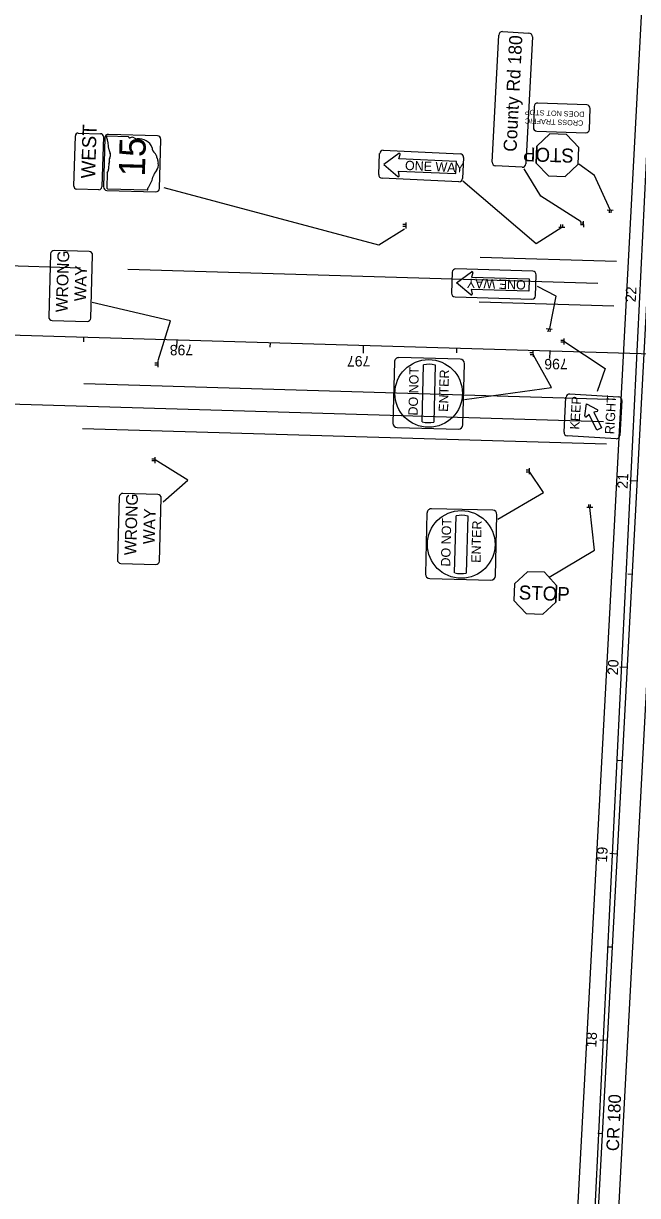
# Model space of a CAD drawing. Extents: x 1658454 to 1663955, y 480219 to 484109.
# Drawn here: x 1661070 to 1661399, y 482260 to 482888 of the extents above; entities that cross this region are included whole.
import ezdxf

# ---------------------------------------------------------------- set-up
doc = ezdxf.new("R2010")
doc.units = 0
for name, color, linetype in [('Default', 7, 'Continuous'), ('PM_P_CL_Double_Solid', 7, 'Continuous'), ('PM_P_Edge_Line', 7, 'Continuous'), ('PM_P_Lane_Line', 7, 'Continuous'), ('PM_X_Lane_Line', 7, 'Continuous'), ('PV_P_EOP', 7, 'Continuous'), ('RW_X_CL_50', 7, 'Continuous'), ('SC_Scratch1', 7, 'Continuous'), ('SN_X_Public', 7, 'Continuous'), ('SN_X_Text', 7, 'Continuous'), ('SV_X_CL_Survey_50', 7, 'Continuous'), ('SV_X_Text', 7, 'Continuous')]:
    doc.layers.add(name, color=color, linetype=linetype)

msp = doc.modelspace()

# ---------------------------------------------------------------- linework, layer by layer
at = {"layer": 'Default'}
for p, q in [((1661102.5, 482720.22), (1661102.43, 482717.83)), ((1661152.48, 482718.74), (1661152.36, 482714.74)), ((1661202.45, 482717.26), (1661202.38, 482714.86)), ((1661252.43, 482715.77), (1661252.31, 482711.77)), ((1661302.41, 482714.29), (1661302.34, 482711.89)), ((1661352.39, 482712.81), (1661352.27, 482708.81)), ((1661399.23, 482643.08), (1661395.24, 482643.3)), ((1661396.56, 482593.15), (1661394.17, 482593.28)), ((1661393.89, 482543.22), (1661389.9, 482543.44)), ((1661391.22, 482493.3), (1661388.82, 482493.42)), ((1661388.55, 482443.37), (1661384.55, 482443.58)), ((1661385.88, 482393.44), (1661383.48, 482393.57)), ((1661383.2, 482343.51), (1661379.21, 482343.72)), ((1661380.53, 482293.58), (1661378.13, 482293.71))]:
    msp.add_line(p, q, dxfattribs=at)
at = {"layer": 'PM_P_CL_Double_Solid'}
msp.add_line((1661344.46, 481619.54), (1661462.56, 483826.39), dxfattribs=at)
at = {"layer": 'PM_P_Edge_Line'}
for p, q in [((1661385.68, 482595.56), (1661398.13, 482828.23)), ((1661388.01, 482760.77), (1661315.12, 482762.93)), ((1661386.72, 482736.8), (1661314.41, 482738.94)), ((1661384.05, 482686.85), (1661102.66, 482695.21)), ((1661382.77, 482662.88), (1661101.95, 482671.22))]:
    msp.add_line(p, q, dxfattribs=at)
at = {"layer": 'PM_P_Lane_Line'}
msp.add_line((1661381.08, 482674.94), (1660395.32, 482704.21), dxfattribs=at)
at = {"layer": 'PM_X_Lane_Line'}
for p, q in [((1661100.95, 482757.29), (1660398.07, 482778.16)), ((1661378.1, 482749.06), (1661126.19, 482756.54))]:
    msp.add_line(p, q, dxfattribs=at)
at = {"layer": 'PV_P_EOP'}
for p, q in [((1661398.13, 482828.23), (1661448.64, 483772.06)), ((1661333.48, 481620.13), (1661385.68, 482595.56)), ((1661355.44, 481618.95), (1661407.64, 482594.38))]:
    msp.add_line(p, q, dxfattribs=at)
at = {"layer": 'RW_X_CL_50'}
msp.add_line((1661341.73, 481544.59), (1661467.43, 484100.93), dxfattribs=at)
at = {"layer": 'SC_Scratch1'}
for p, q in [((1661321.52, 482814.03), (1661325.01, 482882.1)), ((1661327.03, 482883.92), (1661341.17, 482883.2)), ((1661342.99, 482881.18), (1661339.5, 482813.1)), ((1661097.33, 482801.17), (1661098.14, 482828.16)), ((1661099.68, 482829.61), (1661111.67, 482829.26)), ((1661113.13, 482827.71), (1661112.33, 482800.72)), ((1661126.38, 482827.63), (1661115.22, 482827.95)), ((1661126.38, 482827.63), (1661126.38, 482827.63)), ((1661352.33, 482829.1), (1661345.38, 482822.55)), ((1661361.33, 482828.83), (1661352.33, 482829.1)), ((1661367.87, 482821.89), (1661361.33, 482828.83)), ((1661271.48, 482818.65), (1661263.42, 482812.83)), ((1661271.48, 482815.77), (1661272.21, 482818.14)), ((1661345.12, 482813.56), (1661345.38, 482822.55)), ((1661345.38, 482822.55), (1661345.12, 482813.56)), ((1661345.38, 482822.55), (1661345.12, 482813.56)), ((1661367.61, 482812.89), (1661367.87, 482821.89)), ((1661263.42, 482812.83), (1661270.94, 482806.35)), ((1661302.29, 482814.4), (1661271.48, 482815.77)), ((1661302, 482807.85), (1661302.29, 482814.4)), ((1661337.48, 482811.29), (1661323.34, 482812.01)), ((1661345.12, 482813.56), (1661351.66, 482806.61)), ((1661360.66, 482806.34), (1661367.61, 482812.89)), ((1661115.2, 482808.33), (1661114.97, 482800.1)), ((1661271.7, 482806.8), (1661271.19, 482809.21)), ((1661271.19, 482809.21), (1661302, 482807.85)), ((1661351.66, 482806.61), (1661360.66, 482806.34)), ((1661110.78, 482799.27), (1661098.79, 482799.63)), ((1661115.33, 482799.81), (1661136.66, 482799.21)), ((1661302.4, 482749.37), (1661310.37, 482755.29)), ((1661310, 482742.97), (1661302.4, 482749.37)), ((1661311.1, 482754.78), (1661310.42, 482752.41)), ((1661310.42, 482752.41), (1661341.24, 482751.49)), ((1661341.24, 482751.49), (1661341.04, 482744.93)), ((1661341.04, 482744.93), (1661310.22, 482745.85)), ((1661310.22, 482745.85), (1661310.77, 482743.43)), ((1661283.94, 482674.91), (1661284.7, 482705.52)), ((1661290.95, 482705.36), (1661290.19, 482674.75)), ((1661371.15, 482678.12), (1661372.09, 482684.54)), ((1661372.09, 482684.54), (1661377.81, 482681.48)), ((1661377.64, 482680.46), (1661375.87, 482680.17)), ((1661375.87, 482680.17), (1661380.1, 482671.78)), ((1661373.36, 482678.91), (1661372.08, 482677.65)), ((1661377.59, 482670.52), (1661373.36, 482678.91)), ((1661380.1, 482671.78), (1661377.59, 482670.52)), ((1661301.37, 482594.01), (1661302.13, 482624.62)), ((1661308.38, 482624.47), (1661307.62, 482593.86)), ((1661340.48, 482594.63), (1661333.48, 482588.14)), ((1661349.47, 482594.29), (1661340.48, 482594.63)), ((1661355.96, 482587.29), (1661349.47, 482594.29)), ((1661333.48, 482588.14), (1661333.13, 482579.15)), ((1661355.96, 482587.29), (1661355.62, 482578.29)), ((1661355.62, 482578.29), (1661355.96, 482587.29)), ((1661355.62, 482578.29), (1661355.96, 482587.29)), ((1661333.13, 482579.15), (1661339.62, 482572.15)), ((1661348.62, 482571.8), (1661355.62, 482578.29)), ((1661339.62, 482572.15), (1661348.62, 482571.8))]:
    msp.add_line(p, q, dxfattribs=at)
for points in [[(1661343.99, 482843.88), (1661343.56, 482832.64)], [(1661372.16, 482844.68), (1661345.93, 482845.68)], [(1661373.54, 482831.5), (1661373.97, 482842.74)], [(1661345.36, 482830.69), (1661371.59, 482829.7)], [(1661113.93, 482827.07), (1661113.19, 482800.83)], [(1661142.1, 482828.15), (1661115.86, 482828.89)], [(1661143.18, 482799.99), (1661143.92, 482826.23)], [(1661260.68, 482807.33), (1661261.18, 482818.57)], [(1661263.14, 482820.36), (1661304.35, 482818.53)], [(1661306.14, 482816.58), (1661305.64, 482805.34)], [(1661384.67, 482788.48), (1661376.24, 482806.79), (1661367.98, 482813.01)], [(1661369.23, 482782.01), (1661347.47, 482795.78), (1661338.58, 482810.45)], [(1661274.48, 482778.13), (1661260.68, 482769.47), (1661145.63, 482800.28)], [(1661303.68, 482803.55), (1661262.47, 482805.38)], [(1661358.79, 482779.01), (1661344.99, 482770.35), (1661305.8, 482803.81)], [(1661115.01, 482798.9), (1661141.25, 482798.16)], [(1661084.87, 482764.88), (1661083.87, 482731.15)], [(1661105.54, 482766.14), (1661086.8, 482766.7)], [(1661106.36, 482730.48), (1661107.36, 482764.21)], [(1661343.24, 482755.66), (1661302, 482756.88)], [(1661300.07, 482755.06), (1661299.74, 482743.82)], [(1661344.72, 482742.48), (1661345.05, 482753.73)], [(1661142.55, 482707.79), (1661149.07, 482729.1), (1661107.07, 482738.77)], [(1661301.56, 482741.89), (1661342.79, 482740.66)], [(1661085.69, 482729.22), (1661104.43, 482728.66)], [(1661359.88, 482718.12), (1661382.07, 482703.4), (1661377.8, 482691.16)], [(1661269.11, 482707), (1661268.29, 482674.2)], [(1661304.32, 482708.47), (1661271.51, 482709.29)], [(1661305.78, 482673.26), (1661306.6, 482706.07)], [(1661306.66, 482686.8), (1661353.29, 482693.34), (1661343.57, 482710.61)], [(1661359.96, 482669.34), (1661361.02, 482688.06)], [(1661363, 482689.82), (1661389.21, 482688.33)], [(1661390.98, 482686.36), (1661389.91, 482667.64)], [(1661270.57, 482671.8), (1661303.38, 482670.98)], [(1661387.93, 482665.87), (1661361.73, 482667.36)], [(1661145.19, 482632), (1661158.33, 482643.61), (1661140.86, 482654.48)], [(1661324.57, 482622.7), (1661348.94, 482637.13), (1661341.34, 482648.43)], [(1661142.33, 482636), (1661123.59, 482636.55)], [(1661121.66, 482634.73), (1661120.66, 482601)], [(1661143.15, 482600.33), (1661144.15, 482634.07)], [(1661286.54, 482626.11), (1661285.72, 482593.31)], [(1661321.75, 482627.57), (1661288.94, 482628.39)], [(1661323.21, 482592.37), (1661324.03, 482625.17)], [(1661351.95, 482591.68), (1661376.31, 482606.11), (1661373.75, 482629.1)], [(1661122.48, 482599.07), (1661141.22, 482598.51)], [(1661288.01, 482590.91), (1661320.81, 482590.09)]]:
    msp.add_lwpolyline(points, dxfattribs=at)
for centre in [(1661287.44, 482690.13), (1661304.88, 482609.24)]:
    msp.add_circle(centre, 18.12, dxfattribs=at)
for centre, radius, start, end in [((1661326.93, 482882), 1.92, 87.06499, 177.06499), ((1661341.07, 482881.28), 1.92, 357.06499, 87.06499), ((1661345.86, 482843.81), 1.87, 87.8213, 177.8213), ((1661372.09, 482842.81), 1.87, 357.8213, 87.8213), ((1661345.43, 482832.57), 1.87, 177.8213, 267.8213), ((1661371.67, 482831.57), 1.87, 267.8213, 357.8213), ((1661099.64, 482828.11), 1.5, 88.29934, 178.29934), ((1661111.63, 482827.76), 1.5, 358.29934, 88.29934), ((1661115.8, 482827.02), 1.88, 88.38992, 178.38992), ((1661115.16, 482827.64), 0.313, 80.252, 186.12792), ((1661086.38, 482818.74), 29.83, 4.23439, 17.29637), ((1661126.42, 482827.3), 0.335, 17.99373, 96.12405), ((1661127.2, 482827.54), 0.485, 196.3339, 298.72688), ((1661128.52, 482824.42), 2.91, 68.42288, 112.03948), ((1661131.08, 482828.62), 2.12, 225.19641, 275.31951), ((1661132.24, 482819.12), 7.46, 20.6988, 97.37576), ((1661142.04, 482826.28), 1.88, 358.38992, 88.38992), ((1661122.09, 482821.54), 6, 185.7361, 209.15877), ((1661114.76, 482817.72), 2.28, 322.24612, 23.21811), ((1661143.3, 482821.95), 4.09, 182.79304, 230.96667), ((1661139.23, 482816.89), 2.41, 11.26311, 51.66703), ((1661263.06, 482818.49), 1.87, 87.45856, 177.45856), ((1661271.76, 482818.27), 0.471, 343.24118, 125.80058), ((1661304.27, 482816.66), 1.87, 357.45856, 87.45856), ((1661127.26, 482811), 11.35, 168.87661, 183.37819), ((1661115.57, 482813.91), 0.912, 308.18198, 25.49229), ((1661118.07, 482815.18), 1.9, 142.8566, 207.53105), ((1661142.17, 482817.08), 0.641, 154.14165, 221.03834), ((1661138.37, 482812.34), 4.28, 319.09029, 14.68175), ((1661140.05, 482815.08), 2.28, 357.16694, 43.93919), ((1661145.82, 482814.6), 3.51, 174.08504, 199.59986), ((1661323.44, 482813.93), 1.92, 177.06499, 267.06499), ((1661337.58, 482813.2), 1.92, 267.06499, 357.06499), ((1661112.78, 482810.36), 3.16, 320.00942, 359.5018), ((1661119.07, 482812.02), 21.54, 328.80284, 345.58842), ((1661146.41, 482804.82), 6.74, 135.57407, 164.22589), ((1661262.56, 482807.25), 1.87, 177.45856, 267.45856), ((1661271.24, 482806.7), 0.471, 229.08604, 11.70177), ((1661098.83, 482801.12), 1.5, 178.29934, 268.29934), ((1661110.83, 482800.77), 1.5, 268.29934, 358.29934), ((1661115.07, 482800.78), 1.88, 178.38992, 268.38992), ((1661115.29, 482800.13), 0.326, 186.52002, 276.52002), ((1661136.72, 482799.53), 0.329, 260.3483, 346.69653), ((1661137.92, 482800.06), 0.905, 118.1383, 181.66166), ((1661134.54, 482799.64), 2.51, 355.72891, 8.99377), ((1661141.31, 482800.04), 1.88, 268.38992, 358.38992), ((1661303.77, 482805.42), 1.87, 267.45856, 357.45856), ((1661086.74, 482764.83), 1.88, 88.29934, 178.29934), ((1661105.49, 482764.27), 1.88, 358.29934, 88.29934), ((1661301.95, 482755.01), 1.87, 88.29934, 178.29934), ((1661310.65, 482754.91), 0.471, 344.05613, 126.67187), ((1661343.18, 482753.78), 1.87, 358.29934, 88.29934), ((1661301.61, 482743.76), 1.87, 178.29934, 268.29934), ((1661310.31, 482743.33), 0.471, 229.95732, 12.51673), ((1661342.85, 482742.54), 1.87, 268.29934, 358.29934), ((1661085.74, 482731.09), 1.88, 178.29934, 268.29934), ((1661104.48, 482730.53), 1.88, 268.29934, 358.29934), ((1661271.45, 482706.95), 2.34, 88.56558, 178.56558), ((1661287.44, 482690.13), 15.62, 77.02862, 100.10254), ((1661304.26, 482706.12), 2.34, 358.56558, 88.56558), ((1661362.9, 482687.95), 1.87, 86.7482, 176.7482), ((1661389.1, 482686.46), 1.87, 356.7482, 86.7482), ((1661377.55, 482681), 0.547, 279.1104, 61.82744), ((1661270.63, 482674.14), 2.34, 178.56558, 268.56558), ((1661287.44, 482690.13), 15.62, 257.02862, 280.10254), ((1661371.69, 482678.04), 0.547, 171.66896, 314.386), ((1661303.44, 482673.32), 2.34, 268.56558, 358.56558), ((1661361.83, 482669.23), 1.87, 176.7482, 266.7482), ((1661388.04, 482667.74), 1.87, 266.7482, 356.7482), ((1661123.54, 482634.68), 1.88, 88.29934, 178.29934), ((1661142.28, 482634.12), 1.88, 358.29934, 88.29934), ((1661288.89, 482626.05), 2.34, 88.56558, 178.56558), ((1661304.88, 482609.24), 15.62, 77.02862, 100.10254), ((1661321.69, 482625.23), 2.34, 358.56558, 88.56558), ((1661122.53, 482600.94), 1.88, 178.29934, 268.29934), ((1661141.28, 482600.39), 1.88, 268.29934, 358.29934), ((1661288.06, 482593.25), 2.34, 178.56558, 268.56558), ((1661304.88, 482609.24), 15.62, 257.02862, 280.10254), ((1661320.87, 482592.43), 2.34, 268.56558, 358.56558)]:
    msp.add_arc(centre, radius, start, end, dxfattribs=at)
at = {"layer": 'SN_X_Public'}
for p, q in [((1661383.06, 482788.49), (1661386.26, 482788.33)), ((1661384.18, 482788.43), (1661384.1, 482786.84)), ((1661384.66, 482788.41), (1661384.66, 482788.41)), ((1661385.14, 482788.39), (1661385.06, 482786.79)), ((1661275.25, 482780.53), (1661273.65, 482780.53)), ((1661275.25, 482781.65), (1661275.25, 482778.45)), ((1661358.3, 482779.01), (1661358.32, 482780.61)), ((1661359.26, 482779), (1661359.28, 482780.6)), ((1661370.3, 482781.34), (1661368.7, 482781.33)), ((1661370.29, 482782.46), (1661370.32, 482779.26)), ((1661370.31, 482780.86), (1661370.31, 482780.86)), ((1661275.25, 482779.57), (1661273.65, 482779.57)), ((1661275.25, 482780.05), (1661275.25, 482780.05)), ((1661360.38, 482778.99), (1661357.18, 482779.03)), ((1661358.78, 482779.01), (1661358.78, 482779.01)), ((1661370.31, 482780.38), (1661368.71, 482780.37)), ((1661350.47, 482724.89), (1661353.65, 482724.5)), ((1661351.58, 482724.75), (1661351.38, 482723.17)), ((1661352.06, 482724.69), (1661352.06, 482724.69)), ((1661352.54, 482724.63), (1661352.34, 482723.05)), ((1661359.85, 482718.48), (1661358.25, 482718.46)), ((1661359.84, 482719.6), (1661359.86, 482716.4)), ((1661359.85, 482718), (1661359.85, 482718)), ((1661343.33, 482711.83), (1661341.73, 482711.82)), ((1661343.32, 482712.95), (1661343.35, 482709.75)), ((1661359.86, 482717.52), (1661358.26, 482717.5)), ((1661142.33, 482706.31), (1661140.73, 482706.29)), ((1661142.34, 482705.35), (1661140.74, 482705.33)), ((1661142.32, 482707.43), (1661142.34, 482704.23)), ((1661142.33, 482705.83), (1661142.33, 482705.83)), ((1661343.34, 482710.87), (1661341.74, 482710.86)), ((1661343.34, 482711.35), (1661343.34, 482711.35)), ((1661140.73, 482654.93), (1661139.13, 482654.92)), ((1661140.73, 482656.05), (1661140.75, 482652.85)), ((1661140.74, 482653.97), (1661139.14, 482653.96)), ((1661140.74, 482654.45), (1661140.74, 482654.45)), ((1661341.27, 482648.98), (1661339.67, 482648.97)), ((1661341.26, 482650.1), (1661341.29, 482646.9)), ((1661341.28, 482648.02), (1661339.68, 482648.01)), ((1661341.27, 482648.5), (1661341.27, 482648.5)), ((1661373.27, 482629.1), (1661373.27, 482630.7)), ((1661374.23, 482629.1), (1661374.23, 482630.7)), ((1661375.35, 482629.1), (1661372.15, 482629.1)), ((1661373.75, 482629.1), (1661373.75, 482629.1))]:
    msp.add_line(p, q, dxfattribs=at)
at = {"layer": 'SN_X_Text'}
msp.add_lwpolyline([(1661352.37, 482724.89), (1661355.81, 482742.29), (1661345.73, 482747.34)], dxfattribs=at)
at = {"layer": 'SV_X_CL_Survey_50'}
for p, q in [((1661328.12, 481314.2), (1661477.68, 484108.99)), ((1663951.73, 482635.63), (1658453.66, 482798.87))]:
    msp.add_line(p, q, dxfattribs=at)

# ---------------------------------------------------------------- texts
at = {"layer": 'SC_Scratch1'}
for s, height, rotation, p in [('County Rd 180', 7.0009, 87.06499, (1661334.47, 482819.43)), ('DOES NOT STOP', 2.8125, 177.8213, (1661370.93, 482840.98)), ('CROSS TRAFFIC', 2.8125, 177.8213, (1661370.34, 482836.31)), ('WEST', 7.5, 88.29934, (1661108.71, 482805.21)), ('15', 14.063, 88.38992, (1661135.35, 482806.2)), ('STOP', 7.5, 178.29934, (1661365.41, 482821.21)), ('ONE WAY', 5, 357.45856, (1661274.66, 482809.84)), ('WRONG', 6.281, 88.29934, (1661093.89, 482733.53)), ('WAY', 6.281, 88.29934, (1661103.82, 482739.42)), ('ONE WAY', 5, 178.29934, (1661339.55, 482750.76)), ('DO NOT', 5, 88.56558, (1661281.52, 482678.23)), ('ENTER', 5, 88.56558, (1661297.82, 482680.22)), ('KEEP', 5, 86.7482, (1661368.17, 482670.67)), ('RIGHT', 5, 86.7482, (1661386.81, 482668.16)), ('WRONG', 6.281, 88.29934, (1661130.69, 482603.38)), ('WAY', 6.281, 88.29934, (1661140.62, 482609.27)), ('DO NOT', 5, 88.56558, (1661298.95, 482597.34)), ('ENTER', 5, 88.56558, (1661315.26, 482599.33)), ('STOP', 7.5, 357.8213, (1661335.6, 482579.81)), ('CR 180', 6.72, 87.62236, (1661389.33, 482284.13))]:
    msp.add_text(s, height=height, rotation=rotation, dxfattribs=at).set_placement(p)
at = {"layer": 'SV_X_Text'}
for s, rotation, p in [('22', 86.93677, (1661398.38, 482738.89)), ('798', 180.53411, (1661161.22, 482716.21)), ('797', 180.53411, (1661256.16, 482710.23)), ('796', 180.53411, (1661361.9, 482708.7)), ('21', 86.93677, (1661394.01, 482638.97)), ('20', 86.93677, (1661388.79, 482539.13)), ('19', 86.93677, (1661382.97, 482438.78)), ('18', 86.93677, (1661377.24, 482339.56))]:
    msp.add_text(s, height=5.6, rotation=rotation, dxfattribs=at).set_placement(p)

doc.saveas('drawing.dxf')
